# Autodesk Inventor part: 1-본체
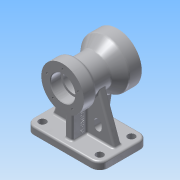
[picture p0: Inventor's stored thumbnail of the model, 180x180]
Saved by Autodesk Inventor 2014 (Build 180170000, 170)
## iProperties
Created: 2015-08
Part Number: 1-본체
Material: 알루미늄 6061
Document SubType Name: Modeling
Designer: study
Density: 2.71 g/cm^3
Appearance: 알루미늄 - 평지
Mass: 1062.86 g
Surface Area: 749.514 cm^2
Volume: 392.199 cm^3
Author: study
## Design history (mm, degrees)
sketch "스케치1"
  geometry: L1 (-61, -40)-(61, -40); L2 (61, -40)-(61, 40); L3 (61, 40)-(-61, 40); L4 (-61, 40)-(-61, -40); L5 (-61, -40)-(61, 40); L6 (61, -40)-(-61, 40); 1 further point
  constraints: 12 end point, 2 midpoint, 2 parallel, 1 horizontal, 1 perpendicular
  dimensions: "d0" = 122 distance of L2.end L3.end; "d1" = 80 distance of L1.end L2.end
extrude "돌출1" new body sketch "스케치1" distance "d2" = 12; taper "d3" = 0 deg
fillet "모깎기1" dims "d4" = 14
sketch "스케치2"
  geometry: L1 (-40, 90)-(50, 90); L2 (-40, 90)-(-40, 125); L3 (-40, 125)-(-20, 125); L4 (-20, 125)-(-14.804, 116); L5 (-14.804, 116)-(13.315, 116); L6 (13.315, 116)-(30, 130); L7 (30, 130)-(50, 130); L8 (50, 130)-(50, 90); L9 (-26, 0)-(26, 0) reference; 2 further points
  constraints: 16 end point, 3 perpendicular, 2 parallel, 1 horizontal, 1 vertical alignment
  dimensions: "d5" = 52 diameter of L5 L1; "d6" = 70 diameter of L3 L1; "d7" = 80 diameter of L7 L1; "d8" = 20 distance of L2.end L3.end; "d9" = 20 distance of L6.end L7.end; "d10" = 90 distance of L1.start L1.end; "d11" = 40 deg angle of L6 L5; "d12" = 60 deg angle of L5 L4; "d13" = 90 distance between parallel lines of L9 L1
revolve "회전1" sketch "스케치2" stored, may be unused: angle "d14" = 90 deg
sketch "스케치3"
  geometry: L1 (-40, 12)-(-26, 12) reference; L2 (-26, 12)-(26, 12) reference; L3 (26, 12)-(40, 12) reference; L4 (-30, 12)-(-30, 71.689); L5 (-30, 71.689)-(40.525, 71.689); L6 (40.525, 71.689)-(30, 12); L7 (-40, 12)-(-40, 0) reference; L8 (40, 0)-(40, 12) reference; L9 (30, 12)-(-30, 12); 1 further point
  constraints: 8 end point, 2 point on line, 1 collinear, 1 parallel, 1 perpendicular
  dimensions: "d15" = 10 distance between parallel lines of L7 L4; "d16" = 10 distance from line of L8 L6.end; "d17" = 80 deg angle of L3 L6; "d18" = 59.6894 distance between parallel lines of L5 L3
extrude "돌출2" join sketch "스케치3" stored distance "d19" = 12; taper "d20" = 0 deg
sketch "스케치4"
  geometry: L1 (-61, 12)-(-47, 12) reference; L2 (-47, 12)-(47, 12) reference; L3 (47, 12)-(61, 12) reference; L4 (-51, 12)-(-21.882, 92); L5 (-21.882, 92)-(21.882, 92); L6 (21.882, 92)-(51, 12); L7 (61, 0)-(61, 12) reference; L8 (-61, 12)-(-61, 0) reference; L9 (-51, 12)-(51, 12); 1 further point
  constraints: 8 end point, 2 point on line, 1 collinear, 1 horizontal
  dimensions: "d21" = 10 distance from line of L7 L6.end; "d22" = 10 distance from line of L8 L4.start; "d23" = 70 deg angle of L2 L6; "d24" = 70 deg angle of L2 L4; "d25" = 80 distance between parallel lines of L3 L5
extrude "돌출3" join sketch "스케치4" stored distance "d26" = 12; taper "d27" = 0 deg
sketch "스케치5"
  geometry: L1 (6, -12)-(51, -12) reference; L2 (6, -64.702)-(6, -12) reference; L3 (18, -30)-(18, -36); L4 (30, -36)-(30, -30); A1 r 26 centre (0, -90) between (25.091, -83.185) and (6, -64.702) reference; A2 r 6 centre (24, -36) between (18, -36) and (30, -36); A3 r 6 centre (24, -30) between (30, -30) and (18, -30); 2 further points
  constraints: 4 end point, 4 point on circle, 4 tangent, 2 centre point, 2 parallel
  dimensions: "d28" = 12 distance between parallel lines of L4 L3; "d29" = 18 dimension on A2 A3; "d30" = 24 horizontal distance of A1.centre A3.centre; "d31" = 18 distance from line of L1 A3.centre
extrude "돌출4" cut sketch "스케치5" stored distance "d32" = 12; taper "d33" = 0 deg
sketch "스케치6"
  geometry: A1 r 14 centre (47, 26) between (61, 26) and (47, 40) reference; A2 r 14 centre (-47, 26) between (-47, 40) and (-61, 26) reference; A3 r 14 centre (-47, -26) between (-61, -26) and (-47, -40) reference; A4 r 14 centre (47, -26) between (47, -40) and (61, -26) reference; 5 further points
  constraints: 4 coincident
hole "구멍1" sketch "스케치6" at (-47, 26), (-47, -26), (47, -26), (47, 26) diameter "d34" = 12; stored, may be unused: countersink angle "d38" = 90 deg, drill point angle "d40" = 118 deg; dims "d35" = 6, "d36" = 4, "d37" = 2, "d39" = 8
hole "구멍2" diameter "d43" = 38; stored, may be unused: countersink angle "d47" = 90 deg, drill point angle "d49" = 0 deg; dims "d41" = 10, "d42" = 10, "d44" = 6, "d45" = 52, "d46" = 20, "d48" = 23
hole "구멍3" diameter "d52" = 32; stored, may be unused: countersink angle "d56" = 90 deg, drill point angle "d58" = 0 deg; dims "d50" = 10, "d51" = 10, "d53" = 6, "d54" = 40, "d55" = 17, "d57" = 23
sketch "스케치7"
  geometry: C1 r 26 at (0, 0) reference; 2 further points
  constraints: 1 vertical alignment
  dimensions: "d59" = 33 distance of point (0, -33) C1.centre
hole "구멍4" sketch "스케치7" at (0, -33) diameter "d60" = 3.242; stored, may be unused: countersink angle "d64" = 90 deg, drill point angle "d66" = 118 deg; dims "d61" = 10, "d62" = 40, "d63" = 17, "d65" = 13
sketch "스케치8"
  geometry: C1 r 20 at (0, 0) reference; 2 further points
  constraints: 1 vertical alignment
  dimensions: "d70" = 27 distance of C1.centre point (0, 27)
hole "구멍5" sketch "스케치8" at (0, 27) diameter "d71" = 3.242; stored, may be unused: countersink angle "d75" = 90 deg, drill point angle "d77" = 118 deg; dims "d72" = 10, "d73" = 40, "d74" = 17, "d76" = 13
sketch "스케치9"
  geometry: L1 (-55.518, -30)-(-12, -30) reference; L2 (-12, -6)-(-12, -30) reference; 2 further points
  constraints: 1 other
  dimensions: "d81" = 16 distance from line of point (-36, -14) L1; "d82" = 24 distance from line of L2 point (-36, -14)
feature "엠보싱1" sketch "스케치9" dims "d0" = 122, "d1" = 80, "d83" = 0.5, "d84" = 0
fillet "모깎기2" dims "d85" = 5, "d86" = 0.3
fillet "모깎기3" dims "d87" = 3
fillet "모깎기4" dims "d88" = 3
chamfer "모따기1" distance "d89" = 1; stored, may be unused: second distance "d90" = 2, angle "d91" = 45 deg
node "솔리드1"
mirror "대칭1"
pattern_circular "원형 패턴1" dims angle "d68" = 360 deg
pattern_circular "원형 패턴2" dims angle "d79" = 360 deg
